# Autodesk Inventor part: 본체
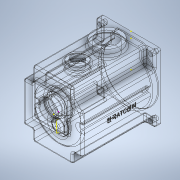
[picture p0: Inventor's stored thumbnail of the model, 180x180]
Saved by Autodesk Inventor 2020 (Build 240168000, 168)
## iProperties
Created: 2022-01
Part Number: 본체
Material: 일반
Document SubType Name: Modeling
Designer: user
Density: 1 g/cm^3
Appearance: 기본값
Mass: 520.096 g
Surface Area: 1170.79 cm^2
Volume: 520.096 cm^3
Author: user
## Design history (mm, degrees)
sketch "스케치1"
  geometry: L1 (-49, 55)-(49, 55); L2 (49, 55)-(49, -55); L3 (49, -55)-(-49, -55); L4 (-49, -55)-(-49, 55); L5 (-49, 55)-(49, -55); L6 (49, 55)-(-49, -55); 1 further point
  constraints: 12 end point, 2 midpoint, 2 parallel, 1 horizontal, 1 perpendicular
  dimensions: "d0" = 98 distance of L2.end L3.end; "d1" = 110 distance of L1.end L2.end
extrude "돌출1" new body sketch "스케치1" distance "d2" = 130; taper "d3" = 0 deg
sketch "스케치2"
  geometry: L1 (-27, 38)-(27, 38); L2 (27, 38)-(27, -16); L3 (27, -16)-(-27, -16); L4 (-27, -16)-(-27, 38); L5 (-27, 38)-(27, -16); L6 (27, 38)-(-27, -16); L7 (49, 55)-(-49, 55) reference; 4 further points
  constraints: 12 end point, 4 midpoint, 2 parallel, 1 horizontal, 1 perpendicular, 1 vertical alignment
  dimensions: "d48" = 11 distance of point (0, 0) point (0, 11); "d49" = 54 distance of L1.start L1.end; "d50" = 54 distance of L1.end L2.end
extrude "돌출2" join sketch "스케치2" distance "d6" = 7; taper "d7" = 0 deg
sketch "스케치3"
  geometry: L1 (0, -130)-(98, -130) reference; L2 (0, -130)-(16, -130); L3 (16, -130)-(16, -10); L4 (16, -10)-(0, -10); L5 (0, -10)-(0, -130); 2 further points
  constraints: 8 end point, 2 parallel, 1 horizontal, 1 perpendicular
  dimensions: "d8" = 16 distance of L4.end L3.end; "d9" = 120 distance of L3.end L2.end
extrude "돌출3" cut sketch "스케치3" distance "d10" = 27; taper "d11" = 0 deg
sketch "스케치4"
  geometry: L1 (-42, 48)-(42, 48); L2 (42, 48)-(42, -48); L3 (42, -48)-(-42, -48); L4 (-42, -48)-(-42, 48); L5 (-42, 48)-(42, -48); L6 (42, 48)-(-42, -48); 5 further points
  constraints: 12 end point, 4 coincident, 2 midpoint, 2 parallel, 1 horizontal, 1 perpendicular
  dimensions: "d12" = 84 distance of L2.end L3.end; "d13" = 96 distance of L1.end L2.end
hole "구멍1" sketch "스케치4" at (-42, 48), (42, 48), (42, -48), (-42, -48) diameter "d14" = 7; stored, may be unused: countersink angle "d18" = 90 deg, drill point angle "d20" = 0 deg; dims "d15" = 20, "d16" = 4, "d17" = 2, "d19" = 20
sketch "스케치5"
  geometry: C1 r 22.5 at (49, -40); C2 r 15 at (49, -89); 1 further point
  constraints: 2 centre point
  dimensions: "d22" = 45 diameter of C1; "d24" = 30 diameter of C2
extrude "돌출4" join sketch "스케치5" distance "d25" = 10; taper "d26" = 0 deg
sketch "스케치9"
  geometry: L1 (-23, 45)-(23, 45); L2 (23, 45)-(23, 16.676); L3 (23, 16.676)-(-23, 16.676); L4 (-23, 16.676)-(-23, 45); L5 (49, -55)-(-49, -55) reference; C1 r 42 at (0, -5); 5 further points
  constraints: 8 end point, 3 midpoint, 2 parallel, 2 vertical alignment, 1 centre point, 1 horizontal, 1 perpendicular
  dimensions: "d32" = 46 distance of L2.end L3.end; "d40" = 84 diameter of C1; "d41" = 50 distance from line of C1.centre L5; "d42" = 50 distance from line of L1 C1.centre
node "작업 평면1"
sketch "스케치11"
  geometry: 1 further point
sketch "스케치12"
  geometry: L1 (98, 10)-(98, 130) reference; L2 (82, 10)-(82, 130) reference; L3 (98, 130)-(82, 130); L4 (82, 130)-(82, 10); L5 (82, 10)-(98, 10); L6 (98, 10)-(98, 130); 3 further points
  constraints: 8 end point, 2 parallel, 1 horizontal, 1 perpendicular
  dimensions: "d36" = 16 distance of L5.end L2.start (derived); "d37" = 120 distance of L2.start L3.end (derived)
extrude "돌출7" cut sketch "스케치12" distance "d38" = 17; taper "d39" = 0 deg
extrude "돌출8" cut sketch "스케치9" distance "d43" = 121; taper "d44" = 0 deg
sketch "스케치14"
  geometry: L1 (23, 45)-(23, 30.143) reference; L2 (-23, 45)-(23, 45) reference; L3 (-23, 30.143)-(-23, 45) reference; L4 (-26, 31.729)-(-26, 48); L5 (-26, 48)-(26, 48); L6 (26, 48)-(26, 31.729); A1 r 42 centre (0, -5) between (-23, 30.143) and (23, 30.143) reference; A2 r 45 centre (0, -5) between (-26, 31.729) and (26, 31.729); 1 further point
  constraints: 6 end point, 2 point on circle, 1 centre point, 3 other
  dimensions: "d45" = 3 radial gap between concentric circles of A1 A2
extrude "돌출9" cut sketch "스케치14" distance "d46" = 9; taper "d47" = 0 deg
sketch "스케치15"
  geometry: L1 (27, 38)-(-27, 38) reference; C1 r 16 at (0, 11); 2 further points
  constraints: 1 centre point, 1 midpoint, 1 vertical alignment
  dimensions: "d51" = 32 diameter of C1; "d52" = 27 distance from line of C1.centre L1
extrude "돌출10" cut sketch "스케치15" distance "d53" = 8.3; taper "d54" = 0 deg
chamfer "모따기1" distance "d55" = 0.8; stored, may be unused: second distance "d56" = 2, angle "d57" = 30 deg
sketch "스케치16"
  geometry: 1 further point
sketch "스케치17"
  geometry: L1 (0, 0)-(0, 11); L2 (0, 0)-(0, -20); C1 r 21 at (0, 11); C2 r 15 at (0, -20); 2 further points
  constraints: 4 end point, 2 centre point, 2 coincident, 2 vertical
  dimensions: "d58" = 11 distance of L1.start L1.end; "d59" = 42 diameter of C1; "d60" = 20 distance of L1.start L2.end; "d61" = 30 diameter of C2
extrude "돌출11" join sketch "스케치17" distance "d62" = 7; taper "d63" = 0 deg
sketch "스케치18"
  geometry: L1 (0, 0)-(0, 11); C1 r 17.5 at (0, 11)
  constraints: 2 end point, 1 centre point, 1 coincident, 1 vertical
  dimensions: "d64" = 11 distance of L1.start L1.end; "d65" = 35 diameter of C1
extrude "돌출12" cut sketch "스케치18" distance "d66" = 10; taper "d67" = 0 deg
sketch "스케치19"
  geometry: L1 (27, 27)-(-27, 27) reference; C1 r 14 at (0, 0); 1 further point
  constraints: 1 centre point
  dimensions: "d68" = 28 diameter of C1; "d69" = 27 distance from line of C1.centre L1
extrude "돌출13" cut sketch "스케치19" stored distance "d70" = 10; taper "d71" = 0 deg
sketch "스케치20"
  geometry: L1 (0, 0)-(0, -20); C1 r 11 at (0, -20)
  constraints: 2 end point, 1 centre point, 1 coincident, 1 vertical
  dimensions: "d72" = 20 distance of L1.start L1.end; "d73" = 22 diameter of C1
extrude "돌출14" cut sketch "스케치20" distance "d74" = 7; taper "d75" = 0 deg
sketch "스케치21"
  geometry: C1 r 11 at (0, 0) reference; C2 r 9.5 at (0, 0); 1 further point
  constraints: 1 centre point, 1 coincident
  dimensions: "d76" = 19 diameter of C2
extrude "돌출15" cut sketch "스케치21" distance "d77" = 3; taper "d78" = 0 deg
sketch "스케치25"
  geometry: 1 further point
sketch "스케치26"
  geometry: 1 further point
sketch "스케치27"
  geometry: 1 further point
sketch "스케치28"
  geometry: C1 r 22.5 at (0, 0) reference; 2 further points
  constraints: 1 coincident
hole "구멍3" sketch "스케치28" at (0, 0) diameter "d87" = 33.376; stored, may be unused: countersink angle "d91" = 90 deg, drill point angle "d93" = 0 deg; dims "d88" = 77, "d89" = 4, "d90" = 2, "d92" = 77
sketch "스케치29"
  geometry: C1 r 15 at (49, -89); C2 r 16.688 at (49, -40) reference; 1 further point
  constraints: 1 centre point, 1 vertical alignment
  dimensions: "d94" = 30 diameter of C1; "d95" = 49 distance of C2.centre C1.centre
extrude "돌출16" join sketch "스케치29" distance "d96" = 5; taper "d97" = 0 deg
sketch "스케치30"
  geometry: C1 r 15 at (23, -32) reference; 1 further point
extrude "돌출17" cut sketch "스케치30" distance "d98" = 5; taper "d99" = 0 deg
sketch "스케치31"
  geometry: C1 r 15 at (0, 0) reference; C2 r 10 at (0, 0); 1 further point
  constraints: 1 centre point, 1 coincident
  dimensions: "d100" = 20 diameter of C2
extrude "돌출18" cut sketch "스케치31" stored distance "d101" = 5; taper "d102" = 0 deg
fillet "모깎기1" dims "d103" = 3
fillet "모깎기2" dims "d104" = 3
sketch "스케치32"
  geometry: 1 further point
sketch "스케치34"
  geometry: L1 (-23, 26.496)-(-23, 45) reference; L2 (23, 45)-(23, 26.496) reference; L3 (-23, 45)-(23, 45) reference; L4 (-36, -1)-(-41.809, -1); L5 (-36, -9)-(-41.809, -9); A1 r 18 centre (0, -20) between (-13.901, -8.565) and (13.901, -8.565) reference; A2 r 24 centre (0, 11) between (13.901, -8.565) and (-13.901, -8.565) reference; A3 r 39 centre (0, -5) between (-23, 26.496) and (23, 26.496) reference; A4 r 4 centre (-36, -5) between (-36, -1) and (-36, -9); A5 r 42 centre (0, -5) between (-23, 30.143) and (23, 30.143) reference; 1 further point
  constraints: 4 end point, 4 point on circle, 2 tangent, 1 centre point, 1 horizontal, 1 horizontal alignment, 1 parallel
  dimensions: "d105" = 36 distance of A4.centre A3.centre; "d106" = 8 diameter of A4
extrude "돌출19" join sketch "스케치34" stored distance "d107" = 5; taper "d108" = 0 deg
sketch "스케치35"
  geometry: A1 r 4 centre (-36, -5) between (-36, -9) and (-36, -1) reference; A2 r 4 centre (36, -5) between (36, -1) and (36, -9) reference; 3 further points
  constraints: 2 coincident
hole "구멍4" sketch "스케치35" at (-36, -5), (36, -5) diameter "d109" = 3.242; stored, may be unused: countersink angle "d113" = 90 deg, drill point angle "d115" = 118 deg; dims "d110" = 7, "d111" = 4, "d112" = 2, "d114" = 9
fillet "모깎기3" dims "d117" = 3
fillet "모깎기4" dims "d118" = 3
fillet "모깎기5" dims "d119" = 3
fillet "모깎기6" dims "d120" = 3
fillet "모깎기7" dims "d121" = 3
fillet "모깎기8" dims "d122" = 3
fillet "모깎기9" dims "d123" = 3
fillet "모깎기10" dims "d124" = 3
fillet "모깎기11" dims "d125" = 3
fillet "모깎기12" dims "d126" = 3
fillet "모깎기13" dims "d127" = 3
fillet "모깎기14" dims "d128" = 3
fillet "모깎기15" dims "d129" = 3
fillet "모깎기16" dims "d130" = 3
fillet "모깎기17" dims "d131" = 3
fillet "모깎기18" dims "d132" = 3
fillet "모깎기19" dims "d133" = 3
fillet "모깎기20" dims "d134" = 3
fillet "모깎기21" dims "d135" = 3
fillet "모깎기22" dims "d136" = 3
fillet "모깎기23" dims "d137" = 3
fillet "모깎기24" dims "d138" = 3
sketch "스케치37"
  geometry: L1 (-10.5, 124)-(-29.5, 124) reference; L2 (-10.5, 121)-(-10.5, 124) reference; L3 (-29.5, 121)-(-29.5, 124) reference; 1 further point
fillet "모깎기25" dims "d139" = 3
fillet "모깎기26" dims "d140" = 3
fillet "모깎기27" dims "d141" = 3
fillet "모깎기28" dims "d142" = 3
fillet "모깎기29" dims "d143" = 3
fillet "모깎기30" dims "d144" = 3
fillet "모깎기31" dims "d145" = 3
chamfer "모따기2" distance "d146" = 1; stored, may be unused: second distance "d147" = 2, angle "d148" = 30 deg
fillet "모깎기32" dims "d149" = 3
fillet "모깎기34" dims "d151" = 6
fillet "모깎기35" dims "d155" = 6
fillet "모깎기36" dims "d156" = 3
fillet "모깎기37" dims "d157" = 6
fillet "모깎기38" dims "d158" = 3
chamfer "모따기4" distance "d159" = 1; stored, may be unused: second distance "d160" = 2, angle "d161" = 30 deg
fillet "모깎기39" dims "d162" = 0.3
chamfer "모따기5" distance "d163" = 1; stored, may be unused: second distance "d164" = 2, angle "d165" = 30 deg
fillet "모깎기40" dims "d166" = 3
sketch "스케치38"
  geometry: L1 (-3, 87)-(-3, 70) reference; L2 (114, 63)-(0, 63) reference; 2 further points
  constraints: 1 other
  dimensions: "d167" = 65 distance from line of L1 point (62, 30); "d168" = 33 distance from line of L2 point (62, 30)
feature "엠보싱1" sketch "스케치38" dims "d169" = 0.5, "d170" = 0
fillet "모깎기41" dims "d171" = 0.3
node "솔리드1"
mirror "미러1"
mirror "미러3"
mirror "미러4"
node "투영된 루프1"
node "투영된 루프3"
feature "A9D066F2-1C7D-4E18-AEED-F7BC21143FA4" dims "d14" = 7, "d15" = 20, "d16" = 4, "d17" = 2, "d18" = 90 deg, "d19" = 20, "d20" = 0
